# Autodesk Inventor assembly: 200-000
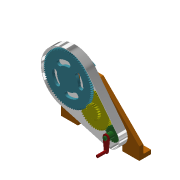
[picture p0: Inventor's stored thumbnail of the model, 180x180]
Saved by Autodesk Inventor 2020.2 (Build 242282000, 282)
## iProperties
Created: 2014-01
Part Number: 200-000
Document SubType Name: Assembly
Designer: F.Stasiak
Manager: www.cadconsulting.pl
Company: Fabian Stasiak CAD Consulting
Author: F.Stasiak
Subject: Zbiór ćwiczeń. Autodesk Inventor 2020. Kurs podstawowy
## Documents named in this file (9)
- C:\2020_Kurs_podstawowy\R6 Zespoły\Warsztat\Gotowe\200-000_Gotowy_W.iam
- C:\2020_Kurs_podstawowy\R6 Zespoły\Warsztat\Komponenty\200-001.ipt
- C:\2020_Kurs_podstawowy\R6 Zespoły\Warsztat\Komponenty\200-004.ipt
- C:\2020_Kurs_podstawowy\R6 Zespoły\Warsztat\Komponenty\200-003.ipt
- C:\2020_Kurs_podstawowy\R6 Zespoły\Warsztat\Komponenty\200-006.ipt
- C:\2020_Kurs_podstawowy\R6 Zespoły\Warsztat\Komponenty\200-007.ipt
- C:\2020_Kurs_podstawowy\R6 Zespoły\Warsztat\Komponenty\200-005.ipt
- C:\2020_Kurs_podstawowy\R6 Zespoły\Warsztat\Komponenty\200-002.ipt
- C:\2020_Kurs_podstawowy\R6 Zespoły\Warsztat\Komponenty\Obudowa.ipt
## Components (9 placed, 8 different names)
1. 200-001:1 — NAPĘD, Wstaw:1, Wstaw:5, Wstaw:7, Równoległy:1
2. 200-006:1 — Wstaw:1, Wstaw:2
3. 200-006:2 — Wstaw:4, Wstaw:7
4. 200-007:1 — Wstaw:5, Wstaw:6
5. Koło z=20 — Wstaw:2, Obrót:3, Zestawiający:1, Zestawiający:2, Zestawiający:3
6. Koło z=20/51 — Wstaw:4, Obrót:3, Obrót:4
7. Koło z=80 — Wstaw:6, Obrót:4
8. 200-005:1 — Zestawiający:1, Zestawiający:2, Zestawiający:3, NAPĘD
9. Obudowa:1 — Równoległy:1
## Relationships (13: Insert 6, Mate 3, RelateRotation 2, Angle 1, Flush 1)
- NAPĘD [Angle]: 200-001:1 ↔ 200-005:1
- Wstaw:1 [Insert]: 200-001:1 ↔ 200-006:1
- Wstaw:2 [Insert]: 200-006:1 ↔ Koło z=20
- Wstaw:4 [Insert]: 200-006:2 ↔ Koło z=20/51
- Wstaw:5 [Insert]: 200-001:1 ↔ 200-007:1
- Obrót:3 [RelateRotation]: Koło z=20 ↔ Koło z=20/51
- Zestawiający:1 [Mate]: Koło z=20 ↔ 200-005:1
- Zestawiający:2 [Mate]: Koło z=20 ↔ 200-005:1
- Zestawiający:3 [Mate]: Koło z=20 ↔ 200-005:1
- Wstaw:6 [Insert]: 200-007:1 ↔ Koło z=80
- Obrót:4 [RelateRotation]: Koło z=20/51 ↔ Koło z=80
- Wstaw:7 [Insert]: 200-001:1 ↔ 200-006:2
- Równoległy:1 [Flush]: 200-001:1 ↔ Obudowa:1
